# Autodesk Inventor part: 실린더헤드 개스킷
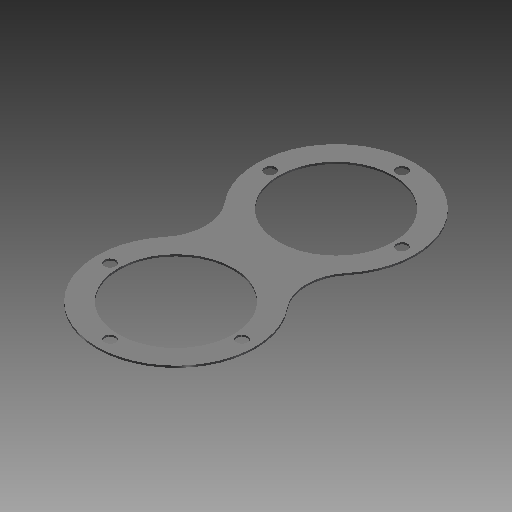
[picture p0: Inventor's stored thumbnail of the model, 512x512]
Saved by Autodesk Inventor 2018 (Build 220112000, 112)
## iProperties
Created: 2019-08
Part Number: 실린더헤드 개스킷
Material: 고무
Document SubType Name: Modeling
Designer: mduedu
Density: 1 g/cm^3
Appearance: 고무 - 검은색 - 버전 1.1
Author: mduedu
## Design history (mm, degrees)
sketch "스케치1"
  geometry: L1 (0, 0)-(0, 85); C1 r 30.5 at (0, 85); C2 r 30.5 at (0, 0); A1 r 42 centre (0, 0) between (0, 42) and (-32.469, 26.642); A2 r 42 centre (0, 85) between (0, 43) and (32.469, 58.358); A3 r 25 centre (51.795, 42.5) between (32.469, 58.358) and (32.469, 26.642); A4 r 25 centre (-51.795, 42.5) between (-32.469, 26.642) and (-32.469, 58.358); A5 r 42 centre (0, 0) between (32.469, 26.642) and (0, 42); A6 r 42 centre (0, 0) between (-32.469, 26.642) and (32.469, 26.642); A7 r 42 centre (0, 85) between (-32.469, 58.358) and (0, 43); A8 r 42 centre (0, 85) between (32.469, 58.358) and (-32.469, 58.358); A9 r 25 centre (51.795, 42.5) between (32.469, 26.642) and (32.469, 58.358); A10 r 25 centre (-51.795, 42.5) between (-32.469, 58.358) and (-32.469, 26.642); 1 further point
  constraints: 20 point on circle, 12 centre point, 4 coincident, 4 tangent, 2 end point, 2 point on line, 1 vertical
  dimensions: "d1" = 84 diameter of A1; "d3" = 85 distance of L1.start L1.end; "d4" = 84 diameter of A2; "d5" = 50 diameter of A3; "d6" = 50 diameter of A4 (= d5); "d11" = 61 diameter of C1; "d12" = 61 diameter of C2
extrude "돌출2" new body sketch "스케치1" distance "d13" = 1; taper "d14" = 0 deg
sketch "스케치2"
  geometry: A1 r 35 centre (0, 0) between (-35, 0) and (0, 35); 2 further points
  constraints: 3 point on circle, 2 horizontal alignment, 1 centre point, 1 coincident, 1 vertical alignment
  dimensions: "d15" = 70 diameter of A1
hole "구멍1" sketch "스케치2" at (-35, 0), (0, 35), (35, 0) diameter "d16" = 6; stored, may be unused: countersink angle "d20" = 90 deg, drill point angle "d22" = 118 deg; dims "d17" = 6, "d18" = 4, "d19" = 2, "d21" = 8
node "작업 평면1"
mirror "대칭1"
node "솔리드2"
other parameters: "d23" = 42.5
